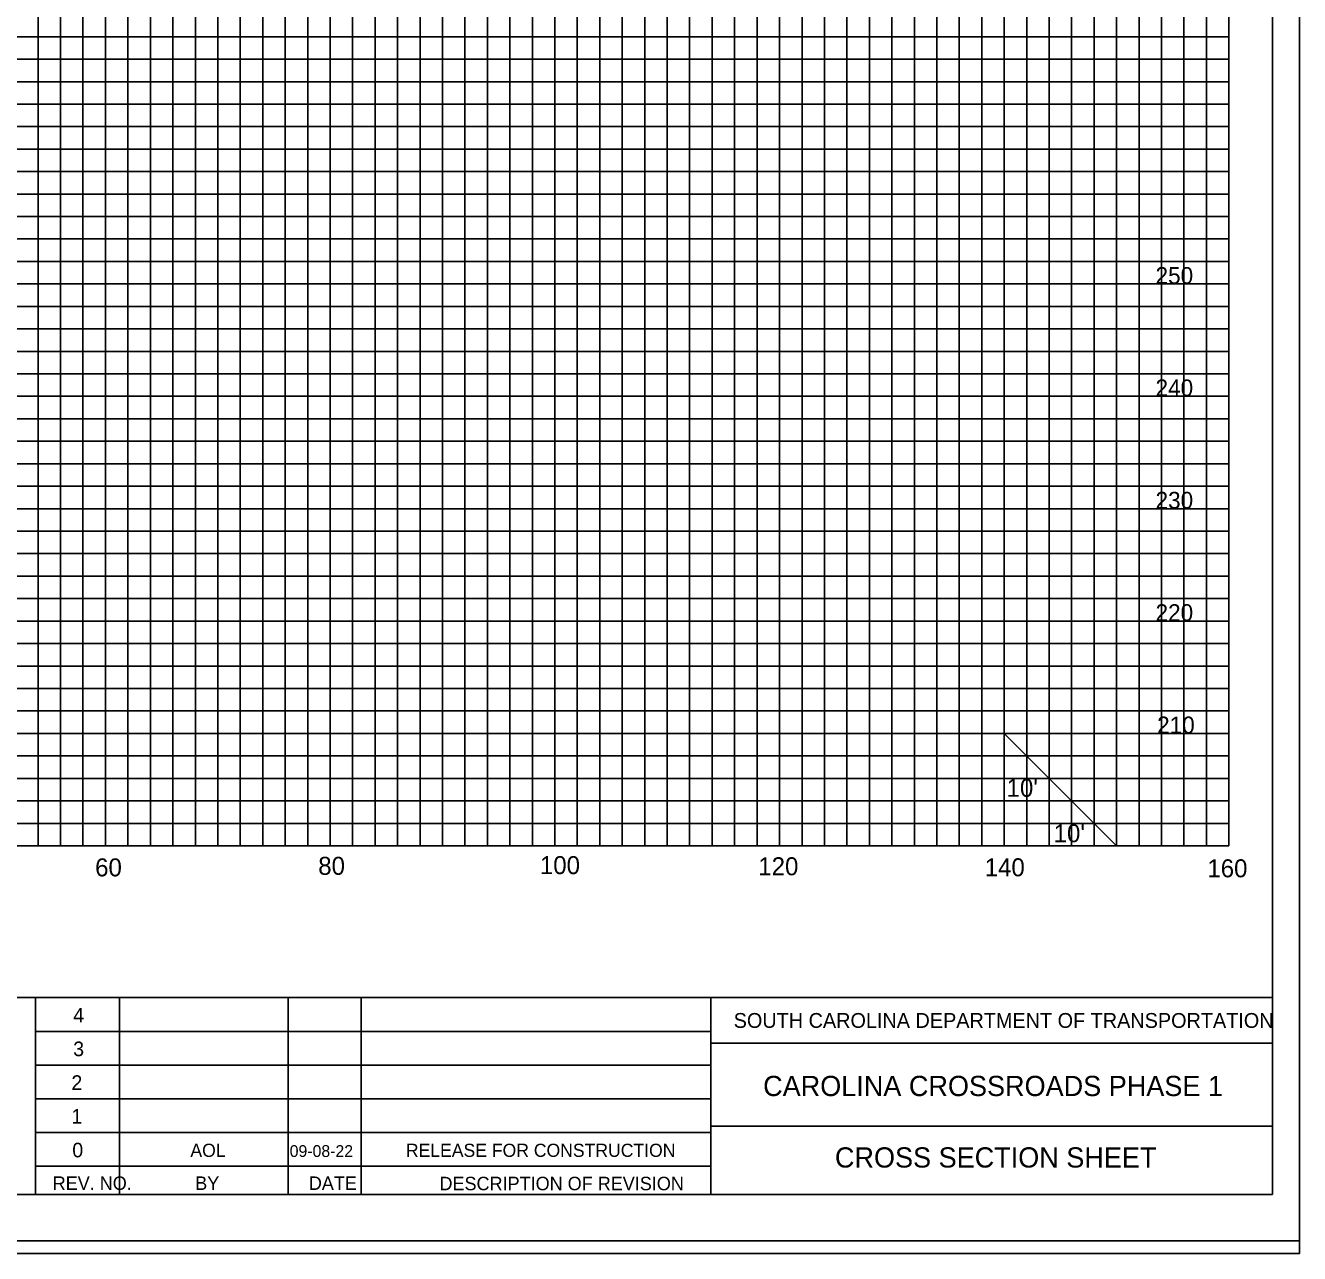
# Model space of a CAD drawing. Extents: x 967 to 1326, y 964 to 1744.
# Drawn here: x 1212.9 to 1326.3, y 1523.7 to 1633 of the extents above; entities that cross this region are included whole.
import ezdxf

# ---------------------------------------------------------------- set-up
doc = ezdxf.new("R2010")
doc.units = 0
for name, color, linetype in [('Default', 7, 'Continuous'), ('RD_PD_PaveShd', 7, 'Continuous'), ('RD_XS_CurbBase', 7, 'Continuous'), ('RD_XS_TieSlope', 7, 'Continuous'), ('RD_XS_TX_Elev_PR', 7, 'Continuous'), ('RD_XS_TX_MkPT', 7, 'Continuous'), ('RD_XS_TX_Slope', 7, 'Continuous'), ('RD_XS_TX_TOC', 7, 'Continuous')]:
    doc.layers.add(name, color=color, linetype=linetype)

msp = doc.modelspace()

# ---------------------------------------------------------------- linework, layer by layer
at = {"layer": 'RD_PD_PaveShd'}
for p, q in [((1323.89, 1738.46), (1323.89, 1528.98)), ((996.11, 1546.49), (1323.89, 1546.49)), ((1213.76, 1528.94), (1213.76, 1546.49)), ((1221.26, 1528.95), (1221.26, 1546.48)), ((1236.26, 1528.95), (1236.26, 1546.48)), ((1242.76, 1528.95), (1242.76, 1546.48)), ((1273.88, 1528.98), (1273.88, 1546.49)), ((1213.76, 1543.48), (1273.88, 1543.48)), ((1323.93, 1542.43), (1273.88, 1542.43)), ((1213.76, 1540.48), (1273.88, 1540.48)), ((1213.76, 1537.48), (1273.88, 1537.48)), ((1213.76, 1534.48), (1273.88, 1534.48)), ((1323.89, 1535.04), (1273.88, 1535.04)), ((1213.76, 1531.48), (1273.88, 1531.48)), ((1323.89, 1528.98), (996.11, 1528.98))]:
    msp.add_line(p, q, dxfattribs=at)
at = {"layer": 'RD_XS_CurbBase'}
msp.add_lwpolyline([(967.41, 1523.72), (1326.28, 1523.72), (1326.28, 1743.72), (967.41, 1743.72)], close=True, dxfattribs=at)
at = {"layer": 'RD_XS_TX_Elev_PR'}
for p, q in [((1220, 1560), (1220, 1730)), ((1230, 1560), (1230, 1730)), ((1240, 1560), (1240, 1730)), ((1250, 1560), (1250, 1730)), ((1260, 1560), (1260, 1730)), ((1270, 1560), (1270, 1730)), ((1280, 1560), (1280, 1730)), ((1290, 1560), (1290, 1730)), ((1300, 1560), (1300, 1730)), ((1310, 1560), (1310, 1730)), ((1320, 1560), (1320, 1730)), ((1000, 1630), (1320, 1630)), ((1000, 1620), (1320, 1620)), ((1000, 1610), (1320, 1610)), ((1000, 1600), (1320, 1600)), ((1000, 1590), (1320, 1590)), ((1000, 1580), (1320, 1580)), ((1000, 1570), (1320, 1570)), ((1000, 1560), (1320, 1560))]:
    msp.add_line(p, q, dxfattribs=at)
at = {"layer": 'RD_XS_TX_MkPT'}
msp.add_line((1300, 1570), (1310, 1560), dxfattribs=at)
at = {"layer": 'RD_XS_TX_Slope'}
for p, q in [((1214, 1560), (1214, 1730)), ((1216, 1560), (1216, 1730)), ((1218, 1560), (1218, 1730)), ((1222, 1560), (1222, 1730)), ((1224, 1560), (1224, 1730)), ((1226, 1560), (1226, 1730)), ((1228, 1560), (1228, 1730)), ((1232, 1560), (1232, 1730)), ((1234, 1560), (1234, 1730)), ((1236, 1560), (1236, 1730)), ((1238, 1560), (1238, 1730)), ((1242, 1560), (1242, 1730)), ((1244, 1560), (1244, 1730)), ((1246, 1560), (1246, 1730)), ((1248, 1560), (1248, 1730)), ((1252, 1560), (1252, 1730)), ((1254, 1560), (1254, 1730)), ((1256, 1560), (1256, 1730)), ((1258, 1560), (1258, 1730)), ((1262, 1560), (1262, 1730)), ((1264, 1560), (1264, 1730)), ((1266, 1560), (1266, 1730)), ((1268, 1560), (1268, 1730)), ((1272, 1560), (1272, 1730)), ((1274, 1560), (1274, 1730)), ((1276, 1560), (1276, 1730)), ((1278, 1560), (1278, 1730)), ((1282, 1560), (1282, 1730)), ((1284, 1560), (1284, 1730)), ((1286, 1560), (1286, 1730)), ((1288, 1560), (1288, 1730)), ((1292, 1560), (1292, 1730)), ((1294, 1560), (1294, 1730)), ((1296, 1560), (1296, 1730)), ((1298, 1560), (1298, 1730)), ((1302, 1560), (1302, 1730)), ((1304, 1560), (1304, 1730)), ((1306, 1560), (1306, 1730)), ((1308, 1560), (1308, 1730)), ((1312, 1560), (1312, 1730)), ((1314, 1560), (1314, 1730)), ((1316, 1560), (1316, 1730)), ((1318, 1560), (1318, 1730)), ((1000, 1632), (1320, 1632)), ((1000, 1628), (1320, 1628)), ((1000, 1626), (1320, 1626)), ((1000, 1624), (1320, 1624)), ((1000, 1622), (1320, 1622)), ((1000, 1618), (1320, 1618)), ((1000, 1616), (1320, 1616)), ((1000, 1614), (1320, 1614)), ((1000, 1612), (1320, 1612)), ((1000, 1608), (1320, 1608)), ((1000, 1606), (1320, 1606)), ((1000, 1604), (1320, 1604)), ((1000, 1602), (1320, 1602)), ((1000, 1598), (1320, 1598)), ((1000, 1596), (1320, 1596)), ((1000, 1594), (1320, 1594)), ((1000, 1592), (1320, 1592)), ((1000, 1588), (1320, 1588)), ((1000, 1586), (1320, 1586)), ((1000, 1584), (1320, 1584)), ((1000, 1582), (1320, 1582)), ((1000, 1578), (1320, 1578)), ((1000, 1576), (1320, 1576)), ((1000, 1574), (1320, 1574)), ((1000, 1572), (1320, 1572)), ((1000, 1568), (1320, 1568)), ((1000, 1566), (1320, 1566)), ((1000, 1564), (1320, 1564)), ((1000, 1562), (1320, 1562))]:
    msp.add_line(p, q, dxfattribs=at)
at = {"layer": 'RD_XS_TX_TOC'}
for points in [[(967.41, 1523.72), (1326.28, 1523.72), (1326.28, 1743.72), (967.41, 1743.72)], [(988.52, 1524.84), (1326.28, 1524.84), (1326.28, 1742.6), (988.52, 1742.6)]]:
    msp.add_lwpolyline(points, close=True, dxfattribs=at)

# ---------------------------------------------------------------- texts
at = {"layer": 'Default'}
for s, p in [('250', (1313.47, 1610)), ('240', (1313.47, 1600)), ('230', (1313.47, 1590)), ('220', (1313.47, 1580)), ('210', (1313.61, 1570))]:
    msp.add_text(s, height=1.5, dxfattribs=at).set_placement(p)
at = {"layer": 'RD_XS_TieSlope'}
for s, height, p in [('AOL', 1.17, (1227.56, 1532.32)), ('09-08-22', 1.053, (1236.4, 1532.31)), ('RELEASE FOR CONSTRUCTION', 1.17, (1246.74, 1532.32))]:
    msp.add_text(s, height=height, dxfattribs=at).set_placement(p)
at = {"layer": 'RD_XS_TX_MkPT'}
for s, height, p in [("10'", 1.6, (1300.21, 1564.36)), ("10'", 1.6, (1304.4, 1560.32)), ('60', 1.6, (1219.08, 1557.28)), ('80', 1.6, (1238.94, 1557.42)), ('100', 1.6, (1258.67, 1557.48)), ('120', 1.6, (1278.11, 1557.38)), ('140', 1.6, (1298.26, 1557.29)), ('160', 1.6, (1318.08, 1557.2)), ('4', 1.3, (1217.13, 1544.28)), ('SOUTH CAROLINA DEPARTMENT OF TRANSPORTATION', 1.32, (1275.92, 1543.8)), ('3', 1.3, (1217.13, 1541.28)), ('2', 1.3, (1216.97, 1538.28)), ('1', 1.3, (1216.97, 1535.28)), ('0', 1.3, (1217.05, 1532.28)), ('REV. NO.', 1.2, (1215.3, 1529.38)), ('BY', 1.2, (1227.99, 1529.38)), ('DATE', 1.2, (1238.1, 1529.38)), ('DESCRIPTION OF REVISION', 1.2, (1249.73, 1529.35))]:
    msp.add_text(s, height=height, dxfattribs=at).set_placement(p)
for s, p in [('CAROLINA CROSSROADS PHASE 1', (1278.54, 1537.73)), ('CROSS SECTION SHEET', (1284.93, 1531.37))]:
    msp.add_text(s, height=1.8, rotation=0, dxfattribs=at).set_placement(p)

doc.saveas('drawing.dxf')
